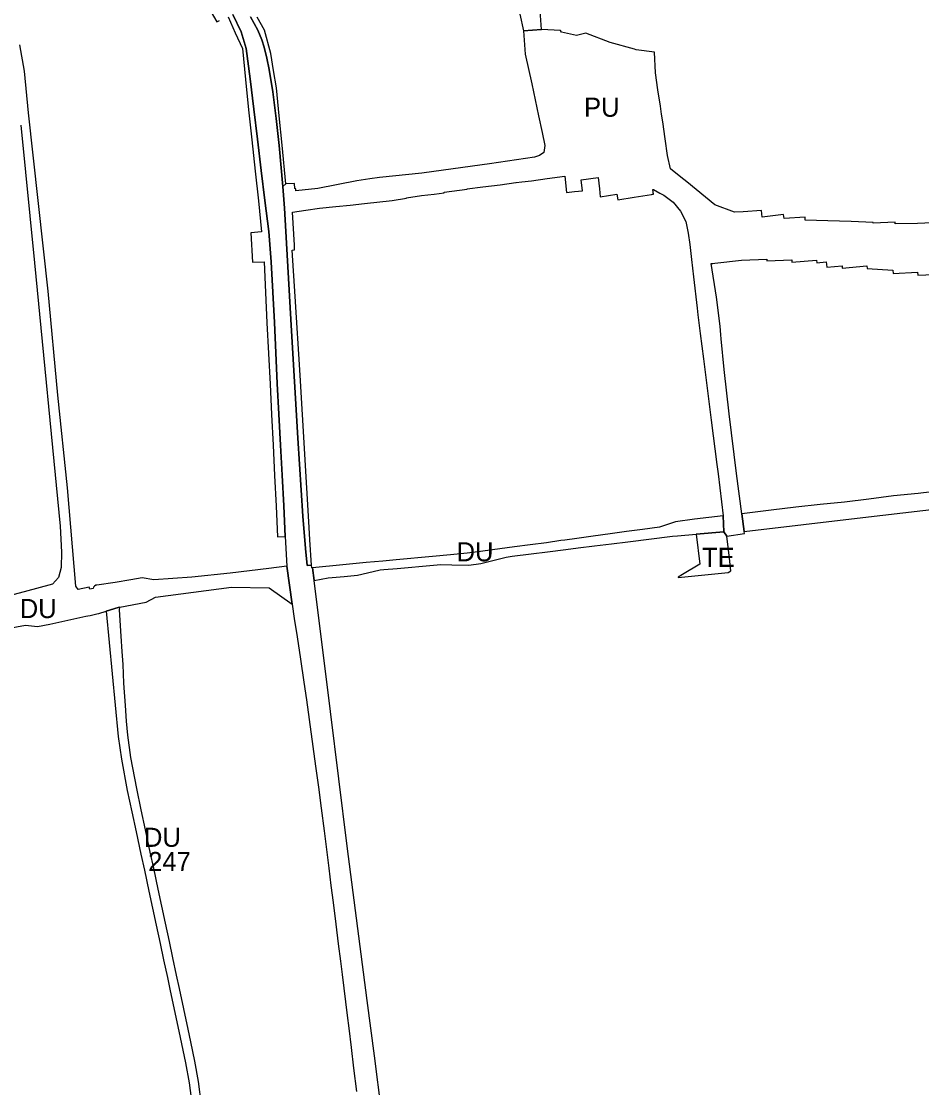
# Model space of a CAD drawing. Extents: x -521047 to -518054, y -1194945 to -1189555.
# Drawn here: x -520050 to -519578, y -1192557 to -1191998 of the extents above; entities that cross this region are included whole.
import ezdxf

# ---------------------------------------------------------------- set-up
doc = ezdxf.new("R2010")
doc.units = 0
for name, color, linetype in [('90310013', 7, 'Continuous'), ('90310023', 7, 'Continuous'), ('90320013', 7, 'Continuous'), ('90400013', 7, 'Continuous'), ('90450013', 7, 'Continuous'), ('ID_navrh', 7, 'Continuous')]:
    doc.layers.add(name, color=color, linetype=linetype)

msp = doc.modelspace()

# ---------------------------------------------------------------- linework, layer by layer
at = {"layer": '90310013'}
for points in [[(-520057.05, -1192316.46), (-520047.46, -1192314.76), (-520041.17, -1192315.39), (-520034.73, -1192314.14), (-520015.86, -1192310.06), (-520014.95, -1192309.86), (-520013.73, -1192309.6), (-520010.2, -1192308.83), (-520009.17, -1192308.52), (-520005.28, -1192307.33), (-519999.05, -1192305.42), (-519998.15, -1192305.25), (-519984.39, -1192302.69), (-519979.44, -1192300.11), (-519939.67, -1192294.88), (-519919.82, -1192295.13), (-519907.89, -1192303.65), (-519910.66, -1192283.8), (-519920.13, -1192284.98), (-519940.37, -1192287.51), (-519960.37, -1192289.48), (-519980.27, -1192290.99), (-519986.42, -1192289.86), (-519992.31, -1192290.88), (-520000.5, -1192292.44), (-520010.19, -1192293.71), (-520010.62, -1192293.75), (-520011.44, -1192294.25), (-520011.84, -1192294.83), (-520012.06, -1192295.49), (-520013.84, -1192295.89), (-520014.1, -1192294.81), (-520019.95, -1192296.1), (-520021.14, -1192294.19), (-520025.53, -1192242.79), (-520030.62, -1192194.2), (-520035.65, -1192139.81), (-520045.89, -1192046.26), (-520048.04, -1192024.54), (-520050.49, -1192010.79)], [(-520050, -1192052.77), (-520042.86, -1192124.96), (-520029.31, -1192262.91), (-520028.62, -1192276.52), (-520028.85, -1192284.58), (-520030.2, -1192289.65), (-520033.35, -1192293.31), (-520048.15, -1192297.25), (-520056.72, -1192299.47)], [(-519566.88, -1192244.15), (-519579.82, -1192245.81), (-519592.74, -1192247.02), (-519605.74, -1192248.7), (-519618.48, -1192250.28), (-519631.14, -1192251.45), (-519643.97, -1192252.95), (-519656.87, -1192254.55), (-519672.27, -1192256.46), (-519670.99, -1192265.56), (-519608.83, -1192258.36), (-519538.54, -1192250.02)], [(-519897.2, -1192284.59), (-519896.33, -1192291.31), (-519888.95, -1192289.92), (-519880.63, -1192289.15), (-519873.68, -1192288.51), (-519868.32, -1192287.24), (-519861.73, -1192285.73), (-519859.77, -1192285.53), (-519852.82, -1192284.97), (-519833.86, -1192283.34), (-519830.01, -1192283), (-519824.22, -1192283.09), (-519815.36, -1192283.3), (-519808.94, -1192282.39), (-519795.72, -1192279.01), (-519792.59, -1192278.63), (-519782.57, -1192277.38), (-519773.99, -1192276.27), (-519764.52, -1192275.08), (-519758.03, -1192274.28), (-519749.43, -1192273.18), (-519740.62, -1192272.07), (-519732.03, -1192270.99), (-519708.66, -1192268.04), (-519705.99, -1192267.85), (-519696.13, -1192267), (-519681.71, -1192265.8), (-519681.98, -1192257.35), (-519697.08, -1192259.23), (-519706.96, -1192260.59), (-519715.34, -1192263.41), (-519724.3, -1192264.56), (-519732.71, -1192265.72), (-519741.32, -1192266.86), (-519750.1, -1192268.09), (-519758.67, -1192269.29), (-519765.04, -1192270.13), (-519767.15, -1192270.44), (-519774.6, -1192271.54), (-519783.18, -1192272.68), (-519791.27, -1192273.73), (-519802.82, -1192275.23), (-519809.24, -1192276.09), (-519816.11, -1192277.01), (-519824.87, -1192277.87), (-519834.23, -1192278.75), (-519853.37, -1192280.53), (-519860.38, -1192281.16), (-519869.09, -1192281.95), (-519881.31, -1192283.11), (-519897.2, -1192284.59)]]:
    msp.add_lwpolyline(points, dxfattribs=at)
at = {"layer": '90310023'}
msp.add_lwpolyline([(-519955.28, -1192565.98), (-519956.83, -1192553.76), (-519958.74, -1192543.03), (-519960.91, -1192532.9), (-519962.3, -1192526.4), (-519966.77, -1192505.11), (-519968.35, -1192498.12), (-519970.29, -1192488.95), (-519972.16, -1192480.36), (-519974.2, -1192470.77), (-519976.11, -1192461.89), (-519978.03, -1192452.91), (-519980.36, -1192442.05), (-519982.18, -1192433.61), (-519984.68, -1192421.85), (-519986.9, -1192411.41), (-519989.29, -1192400.26), (-519992.38, -1192384.09), (-519994.01, -1192372.39), (-519994.62, -1192364.98), (-519995.09, -1192356.86), (-519995.98, -1192345.16), (-519996.45, -1192335.23), (-519996.92, -1192328.48), (-519997.42, -1192320.41), (-519998.28, -1192306.62), (-519998.15, -1192305.25), (-519999.05, -1192305.42), (-520005.28, -1192307.33), (-519998.98, -1192372.94), (-519997.31, -1192384.9), (-519994.19, -1192401.25), (-519991.79, -1192412.45), (-519989.57, -1192422.89), (-519987.07, -1192434.66), (-519985.25, -1192443.1), (-519982.92, -1192453.96), (-519981, -1192462.94), (-519979.09, -1192471.82), (-519977.05, -1192481.41), (-519975.18, -1192490), (-519973.23, -1192499.19), (-519971.66, -1192506.17), (-519967.19, -1192527.44), (-519965.8, -1192533.95), (-519963.65, -1192543.99), (-519961.77, -1192554.51), (-519960.25, -1192566.55)], dxfattribs=at)
at = {"layer": '90320013'}
for points in [[(-519938.91, -1191994.89), (-519934.5, -1192003.88), (-519931.87, -1192012.61), (-519929.91, -1192028.54), (-519927.96, -1192044.44), (-519926.02, -1192060.18), (-519924.01, -1192076.47), (-519922.08, -1192092.17), (-519920.08, -1192108.45), (-519918.83, -1192124.31), (-519917.95, -1192140.26), (-519917.06, -1192156.18), (-519916.46, -1192172.13), (-519915.62, -1192188.19), (-519914.78, -1192204.1), (-519913.92, -1192220.36), (-519913.08, -1192236.19), (-519912.24, -1192252.18), (-519911.44, -1192268.22), (-519910.66, -1192283.8), (-519907.89, -1192303.65), (-519906.74, -1192311.24), (-519905.16, -1192320.75), (-519903.52, -1192332.49), (-519901.65, -1192344.58), (-519900.24, -1192353.9), (-519895.56, -1192388.49), (-519894.12, -1192399.59), (-519892.69, -1192410.59), (-519891.14, -1192422.37), (-519890.02, -1192430.9), (-519888.69, -1192441.94), (-519887.51, -1192450.99), (-519886.39, -1192459.97), (-519884.97, -1192471.33), (-519883.69, -1192481.55), (-519882.55, -1192490.66), (-519881.65, -1192497.64), (-519879, -1192519.17), (-519878.19, -1192525.73), (-519876.95, -1192535.97), (-519875.66, -1192546.69), (-519874.18, -1192558.92)], [(-519861, -1192569.32), (-519864.74, -1192540.33), (-519868.46, -1192511.25), (-519879.01, -1192430.53), (-519887.75, -1192359.93), (-519896.33, -1192291.31), (-519897.2, -1192284.59), (-519897.58, -1192284.63), (-519897.66, -1192283.33), (-519900.05, -1192283.53), (-519900.91, -1192274.59), (-519902.22, -1192257.63), (-519904.86, -1192216.76), (-519908.32, -1192157.63), (-519911.8, -1192096.26), (-519912.71, -1192084.91), (-519914.69, -1192063.46), (-519916.23, -1192049.3), (-519917.98, -1192035.41), (-519919.89, -1192023.56), (-519921.04, -1192017.68), (-519922.52, -1192011.89), (-519923.7, -1192008.08), (-519925.88, -1192003.11), (-519929.61, -1191996.06)]]:
    msp.add_lwpolyline(points, dxfattribs=at)
at = {"layer": '90400013'}
msp.add_lwpolyline([(-519705.65, -1192289.69), (-519679.44, -1192287.03), (-519677.99, -1192286.33), (-519678.64, -1192279.67), (-519680.1, -1192268.07), (-519681.71, -1192265.8), (-519696.13, -1192267), (-519694.21, -1192282.82), (-519703.27, -1192288.12), (-519705.67, -1192289.48), (-519705.65, -1192289.69)], dxfattribs=at)
at = {"layer": '90450013'}
for points in [[(-519788.63, -1191994.63), (-519786.7, -1192003.43), (-519777.19, -1192002.68), (-519778.7, -1191980.47)], [(-519950.32, -1191993.61), (-519947.28, -1191998.71), (-519945.87, -1191998.03)], [(-519941.43, -1191996.02), (-519937.63, -1192004.36), (-519933.83, -1192012.71), (-519932.31, -1192028.79), (-519930.68, -1192044.72), (-519929.04, -1192060.52), (-519927.2, -1192076.81), (-519925.51, -1192092.5), (-519923.97, -1192108.74), (-519929.46, -1192109.15), (-519928.54, -1192124.57), (-519922.53, -1192124.41), (-519921.8, -1192140.44), (-519921.16, -1192156.36), (-519920.15, -1192172.34), (-519919.39, -1192188.39), (-519918.66, -1192204.29), (-519917.86, -1192220.37), (-519917.02, -1192236.36), (-519916.24, -1192252.38), (-519915.44, -1192268.38)], [(-519915.44, -1192268.38), (-519911.44, -1192268.22), (-519912.24, -1192252.18), (-519913.08, -1192236.19), (-519913.92, -1192220.36), (-519914.78, -1192204.1), (-519915.62, -1192188.19), (-519916.46, -1192172.13), (-519917.06, -1192156.18), (-519917.95, -1192140.26), (-519918.83, -1192124.31), (-519920.08, -1192108.45), (-519922.08, -1192092.17), (-519924.01, -1192076.47), (-519926.02, -1192060.18), (-519927.96, -1192044.44), (-519929.91, -1192028.54), (-519931.87, -1192012.61), (-519934.5, -1192003.88), (-519938.91, -1191994.89)], [(-519929.61, -1191996.06), (-519925.88, -1192003.11), (-519923.7, -1192008.08), (-519922.52, -1192011.89), (-519921.04, -1192017.68), (-519919.89, -1192023.56), (-519917.98, -1192035.41), (-519916.23, -1192049.3), (-519914.69, -1192063.46), (-519912.71, -1192084.91), (-519911.11, -1192083.54), (-519913.06, -1192063.26), (-519914.59, -1192047.98), (-519916.07, -1192033.16), (-519917.56, -1192024.18), (-519919.05, -1192015.17), (-519922.3, -1192002.97), (-519926.15, -1191996.16)], [(-519568.5, -1192103.84), (-519580.3, -1192104.25), (-519591.99, -1192104.56), (-519591.94, -1192103.69), (-519603.5, -1192104.08), (-519603.5, -1192103.75), (-519615.05, -1192103.33), (-519627.12, -1192102.98), (-519639.01, -1192102.6), (-519639.06, -1192100.98), (-519650.04, -1192101.74), (-519650.37, -1192099.65), (-519661.53, -1192101.02), (-519661.98, -1192097.41), (-519671.64, -1192098.27), (-519676.12, -1192098.3), (-519686.39, -1192094.47), (-519701.13, -1192082.56), (-519704.26, -1192080.03), (-519709.65, -1192075.67), (-519711.12, -1192068.66), (-519712.45, -1192059.93), (-519713.73, -1192051.1), (-519714.32, -1192047.07), (-519714.93, -1192042.91), (-519716.21, -1192034.2), (-519717.52, -1192025.39), (-519717.99, -1192014.61), (-519727.68, -1192013.31), (-519728.43, -1192013.03), (-519741.32, -1192009.54), (-519753.96, -1192004.68), (-519758.94, -1192005.78), (-519766.67, -1192004.16), (-519767.19, -1192003.23), (-519777.19, -1192002.68), (-519786.7, -1192003.43), (-519785.75, -1192015.53), (-519782.36, -1192031.23), (-519778.75, -1192047.93), (-519776.89, -1192056.66), (-519775.45, -1192063.43), (-519776.06, -1192067.05), (-519778.25, -1192068.69), (-519780.86, -1192069.53), (-519804.43, -1192073.1), (-519808.22, -1192073.64), (-519839.93, -1192077.93), (-519862.13, -1192080.18), (-519867.18, -1192080.97), (-519873.88, -1192081.95), (-519894.45, -1192085.96), (-519905.99, -1192087.26), (-519905.94, -1192086.06), (-519906.45, -1192086.02), (-519906.69, -1192083.39), (-519911.11, -1192083.54), (-519912.71, -1192084.91), (-519911.8, -1192096.26), (-519908.32, -1192157.63), (-519904.86, -1192216.76), (-519902.22, -1192257.63), (-519900.91, -1192274.59), (-519900.05, -1192283.53), (-519897.66, -1192283.33), (-519898.52, -1192270.07), (-519898.94, -1192263.63), (-519903.7, -1192183.77), (-519906.33, -1192142.46), (-519907.88, -1192118.23), (-519906.53, -1192118.16), (-519906.68, -1192115.59), (-519907.7, -1192098.39), (-519900.6, -1192097.36), (-519893.5, -1192096.32), (-519885.04, -1192095.42), (-519877.41, -1192094.62), (-519869.88, -1192093.86), (-519855.42, -1192092.27), (-519847.87, -1192091.12), (-519847.9, -1192090.92), (-519840.16, -1192089.72), (-519833.48, -1192088.86), (-519828.18, -1192088.18), (-519828.21, -1192087.86), (-519816.14, -1192086.25), (-519816.08, -1192086.11), (-519807.87, -1192085.12), (-519798.92, -1192084.02), (-519790.73, -1192082.85), (-519790.43, -1192082.82), (-519787.48, -1192082.48), (-519782.51, -1192081.92), (-519774.18, -1192080.69), (-519765.06, -1192079.58), (-519764.03, -1192088.02), (-519759.92, -1192087.6), (-519755.8, -1192087.17), (-519756.4, -1192081.36), (-519747.49, -1192080.23), (-519746.86, -1192086.22), (-519746.5, -1192090.3), (-519737.77, -1192088.95), (-519737.28, -1192091.93), (-519728.68, -1192090.5), (-519719.53, -1192089.03), (-519719.03, -1192088.95), (-519718.54, -1192088.87), (-519718.88, -1192086.43), (-519718.49, -1192086.54), (-519715.18, -1192088.33), (-519713.13, -1192089.43), (-519708.3, -1192093.18), (-519704.34, -1192097.82), (-519701.52, -1192103.24), (-519700.31, -1192109.31), (-519699.43, -1192115.26), (-519698.68, -1192123.2), (-519697.56, -1192132.24), (-519695.67, -1192148.71), (-519695.24, -1192152.2), (-519694.02, -1192161.88), (-519692.27, -1192175.27), (-519688.26, -1192207.37), (-519685.37, -1192230.59), (-519684.65, -1192235.35), (-519681.98, -1192257.35), (-519681.71, -1192265.8), (-519680.1, -1192268.07), (-519670.87, -1192266.69), (-519670.99, -1192265.56), (-519672.27, -1192256.46), (-519675.09, -1192235.33), (-519678.87, -1192203.93), (-519681.55, -1192180.82), (-519683.08, -1192164.71), (-519683.32, -1192162.62), (-519683.69, -1192158.15), (-519685.52, -1192142.97), (-519688.41, -1192125.33), (-519687.38, -1192125.21), (-519686.34, -1192125.09), (-519672.36, -1192123.5), (-519659.25, -1192122.91), (-519659.16, -1192123.93), (-519646.13, -1192123.42), (-519646.04, -1192124.51), (-519633.16, -1192123.44), (-519633, -1192124.83), (-519628.09, -1192124.34), (-519627.8, -1192127.24), (-519619.75, -1192126.48), (-519619.63, -1192127.72), (-519606.81, -1192126.53), (-519606.68, -1192127.88), (-519593.07, -1192128.78), (-519592.97, -1192130.42), (-519580.18, -1192129.88), (-519580.06, -1192131.4), (-519567.37, -1192130.77)]]:
    msp.add_lwpolyline(points, dxfattribs=at)

# ---------------------------------------------------------------- texts
at = {"layer": '90310013'}
for rotation, p in [(0, (-519821.68, -1192281.27)), (360, (-520050.54, -1192310.99))]:
    msp.add_text('DU', height=10, rotation=rotation, dxfattribs=at).set_placement(p)
at = {"layer": '90310023'}
msp.add_text('DU', height=10, rotation=360, dxfattribs=at).set_placement((-519985.46, -1192430.82))
at = {"layer": '90400013'}
msp.add_text('TE', height=10, rotation=0, dxfattribs=at).set_placement((-519693.07, -1192284.15))
at = {"layer": '90450013'}
msp.add_text('PU', height=10, rotation=0, dxfattribs=at).set_placement((-519754.92, -1192048.39))
at = {"layer": 'ID_navrh'}
msp.add_text('247', height=10, rotation=360, dxfattribs=at).set_placement((-519983.26, -1192443.51))

doc.saveas('drawing.dxf')
